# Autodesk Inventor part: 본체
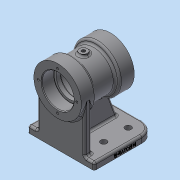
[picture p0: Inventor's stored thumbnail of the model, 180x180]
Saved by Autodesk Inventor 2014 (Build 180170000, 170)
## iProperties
Created: 2020-06
Part Number: 본체
Material: Generic
Document SubType Name: Modeling
Designer: kh
Density: 1 g/cm^3
Appearance: Default
Mass: 268.673 g
Surface Area: 641.497 cm^2
Volume: 268.673 cm^3
Author: kh
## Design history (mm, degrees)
sketch "Sketch1"
  geometry: L1 (-90, -49)-(0, -49); L2 (0, -49)-(0, 49); L3 (0, 49)-(-90, 49); L4 (-90, 49)-(-90, -49); 2 further points
  constraints: 8 end point, 2 coincident, 2 parallel, 1 horizontal, 1 midpoint, 1 perpendicular
  dimensions: "d0" = 98 distance of L1.end L2.end; "d1" = 90 distance of L1.start L1.end
extrude "Extrusion1" new body sketch "Sketch1" distance "d2" = 10; taper "d3" = 0 deg
workplane "Work Plane1"
sketch "Sketch2"
  geometry: L1 (0, 0)-(98, 0) reference; L2 (98, 0)-(98, 10) reference; L3 (0, 10)-(98, 10) reference; L4 (0, 0)-(0, 10) reference; C1 r 35 at (49, 80); 2 further points
  constraints: 1 centre point, 1 midpoint, 1 vertical alignment
  dimensions: "d5" = 70 diameter of C1; "d6" = 80 distance from line of C1.centre L1
extrude "Extrusion2" join sketch "Sketch2" distance "d7" = 78; taper "d8" = 0 deg
sketch "Sketch5"
  geometry: L1 (17, 115)-(51, 115); L2 (90, 10)-(90, 0) reference; L3 (90, 0)-(0, 0) reference; L4 (0, 0)-(0, 10) reference; L5 (0, 10)-(90, 10) reference; L6 (17, 115)-(17, 109); L7 (17, 109)-(51, 109); L8 (51, 109)-(51, 115); L9 (-5, 80)-(73, 80); L10 (73, 45)-(-5, 45) reference; L11 (-5, 45)-(-5, 115) reference; L12 (-5, 115)-(73, 115) reference; L13 (73, 115)-(73, 45) reference; 2 further points
  constraints: 10 end point, 3 perpendicular, 2 coincident, 1 horizontal, 1 midpoint
  dimensions: "d19" = 34 distance of L1.start L1.end; "d20" = 6 distance of L1.start L6.end
revolve "Revolution1" sketch "Sketch5" stored, may be unused: angle "d21" = 90 deg
sketch "Sketch3"
  geometry: L1 (60.74, 57.42)-(78, 10); L2 (-5, 45)-(73, 45) reference; L3 (90, 0)-(0, 0) reference; L4 (0, 0)-(0, 10) reference; L5 (90, 10)-(0, 10) reference; L6 (90, 0)-(90, 10) reference; L7 (0, 10)-(0, 57.42); L8 (0, 57.42)-(60.74, 57.42); L9 (0, 10)-(78, 10); 1 further point
  constraints: 8 end point, 2 parallel, 2 point on line, 1 perpendicular
  dimensions: "d9" = 47.42046 distance of L7.start L7.end; "d10" = 12 distance of L5.start L1.end; "d11" = 70 deg angle of L5 L1
extrude "Extrusion3" join sketch "Sketch3" stored distance "d12" = 10; taper "d13" = 0 deg
sketch "Sketch4"
  geometry: L1 (98, 0)-(98, 10) reference; L2 (54, 10)-(98, 10) reference; L3 (0, 10)-(44, 10) reference; L4 (14, 80)-(14, 10); L5 (84, 80)-(84, 10); L6 (14, 80)-(84, 80); L7 (14, 10)-(84, 10); A1 r 35 centre (49, 80) between (14, 80) and (84, 80) reference; 1 further point
  constraints: 8 end point, 2 point on circle, 2 point on line, 2 tangent, 1 parallel
  dimensions: "d15" = 70 distance of L5.end L4.end
extrude "Extrusion4" join sketch "Sketch4" distance "d16" = 10; taper "d17" = 0 deg
sketch "Sketch6"
  geometry: L1 (90, 10)-(90, 0) reference; L2 (90, 0)-(0, 0) reference; L3 (0, 0)-(0, 45) reference; L4 (0, 45)-(-5, 45) reference; L5 (-5, 45)-(-5, 115) reference; L6 (-5, 115)-(17, 115) reference; L7 (17, 115)-(17, 109) reference; L8 (17, 109)-(51, 109) reference; L9 (51, 109)-(51, 115) reference; L10 (51, 115)-(73, 115) reference; L11 (73, 115)-(73, 45) reference; L12 (73, 45)-(65.261, 45) reference; L13 (65.261, 45)-(78, 10) reference; L14 (78, 10)-(90, 10) reference; L15 (-5, 80)-(73, 80); L16 (-5, 80)-(-5, 103.5); L17 (-5, 103.5)-(13, 103.5); L18 (13, 103.5)-(13, 100); L19 (13, 100)-(19, 100); L20 (19, 100)-(19, 103); L21 (19, 103)-(49, 103); L22 (49, 103)-(49, 100); L23 (49, 100)-(55, 100); L24 (55, 100)-(55, 103.5); L25 (55, 103.5)-(73, 103.5); L26 (73, 80)-(73, 103.5)
  constraints: 24 end point, 6 parallel, 3 perpendicular, 2 midpoint, 2 point on line, 1 collinear
  dimensions: "d22" = 47 diameter of L17 L15; "d23" = 40 diameter of L19 L15; "d24" = 46 diameter of L21 L15; "d25" = 40 diameter of L23 L15; "d26" = 47 diameter of L25 L15; "d27" = 18 distance of L16.end L17.end; "d28" = 6 distance of L18.end L19.end; "d29" = 30 distance of L20.end L21.end; "d30" = 18 distance of L24.end L25.end
revolve "Revolution2" sketch "Sketch6" stored, may be unused: angle "d31" = 90 deg
workplane "Work Plane3"
sketch "Sketch7"
  geometry: L1 (-5, -35)-(-5, 35) reference; C1 r 6 at (33, 0); 1 further point
  constraints: 1 centre point, 1 horizontal alignment
  dimensions: "d33" = 38 distance from line of C1.centre L1; "d36" = 12 diameter of C1
extrude "Extrusion5" join sketch "Sketch7" stored distance "d34" = 10; taper "d35" = 0 deg
hole "Hole1" diameter "d39" = 5.188; stored, may be unused: countersink angle "d43" = 90 deg, drill point angle "d45" = 118 deg; dims "d37" = 10, "d38" = 10, "d40" = 6, "d41" = 4, "d42" = 2, "d44" = 13.25
sketch "Sketch8"
  geometry: C1 r 23.5 at (0, 0) reference; 2 further points
  constraints: 1 vertical alignment
  dimensions: "d46" = 28.5 distance of C1.centre point (0, 28.5)
hole "Hole2" sketch "Sketch8" at (0, 28.5) diameter "d47" = 3.242; stored, may be unused: countersink angle "d51" = 90 deg, drill point angle "d53" = 118 deg; dims "d48" = 10, "d49" = 4, "d50" = 2, "d52" = 12
pattern_circular "Circular Pattern1" dims angle "d55" = 360 deg
workplane "Work Plane4"
mirror "Mirror1"
sketch "Sketch9"
  geometry: L1 (0, 49)-(0, 35) reference; 5 further points
  constraints: 2 horizontal alignment, 2 vertical alignment
  dimensions: "d57" = 70 distance from line of point (70, 29) L1; "d58" = 29 vertical distance of point (70, 29) point (0, 0); "d59" = 36 distance of point (70, 29) point (34, 29); "d60" = 29 vertical distance of point (70, -29) point (0, 0) (= d58)
hole "Hole3" sketch "Sketch9" at (34, 29), (70, 29), (70, -29), (34, -29) diameter "d61" = 9; stored, may be unused: countersink angle "d65" = 90 deg, drill point angle "d67" = 118 deg; dims "d62" = 10, "d63" = 4, "d64" = 2, "d66" = 12
fillet "Fillet1" dims "d68" = 3
fillet "Fillet2" dims "d69" = 3
fillet "Fillet3" dims "d70" = 3
fillet "Fillet4" dims "d71" = 20
fillet "Fillet5" dims "d72" = 3
fillet "Fillet6" dims "d73" = 3
fillet "Fillet7" dims "d74" = 3
fillet "Fillet8" dims "d75" = 3
fillet "Fillet9" dims "d76" = 0.3
sketch "Sketch10"
  geometry: L1 (0, 0)-(67, 0) reference; L2 (0, 0)-(0, 7) reference; L3 (0, 7)-(67, 7) reference; L4 (67, 0)-(67, 7) reference; L5 (67, 0)-(0, 0) reference; L6 (0, 0)-(0, 7) reference; L7 (0, 7)-(67, 7) reference; L8 (67, 0)-(67, 7) reference; L9 (67, 0)-(0, 0) reference; L10 (0, 0)-(0, 7) reference; L11 (0, 7)-(67, 7) reference; L12 (67, 0)-(67, 7) reference; L13 (67, 0)-(0, 0) reference; L14 (-3, 7)-(-3, 0) reference; 1 further point
  constraints: 1 other
  dimensions: "d77" = 4 distance from line of point (42, 4) L1; "d78" = 45 distance from line of point (42, 4) L14
emboss "Emboss1" sketch "Sketch10" dims "d0" = 98, "d1" = 90, "d79" = 0.5, "d80" = 0
chamfer "Chamfer1" distance "d81" = 1; stored, may be unused: second distance "d82" = 2, angle "d83" = 45 deg
fillet "Fillet10" dims "d84" = 3
body "Solid1"
node "Projected Loop1"
node "Projected Loop2"
node "Project Cut Edges1"
node "Project Cut Edges2"
node "Project Cut Edges3"
node "Project Cut Edges4"
node "Project Cut Edges5"
other parameters: "d4" = 5, "d32" = -112
